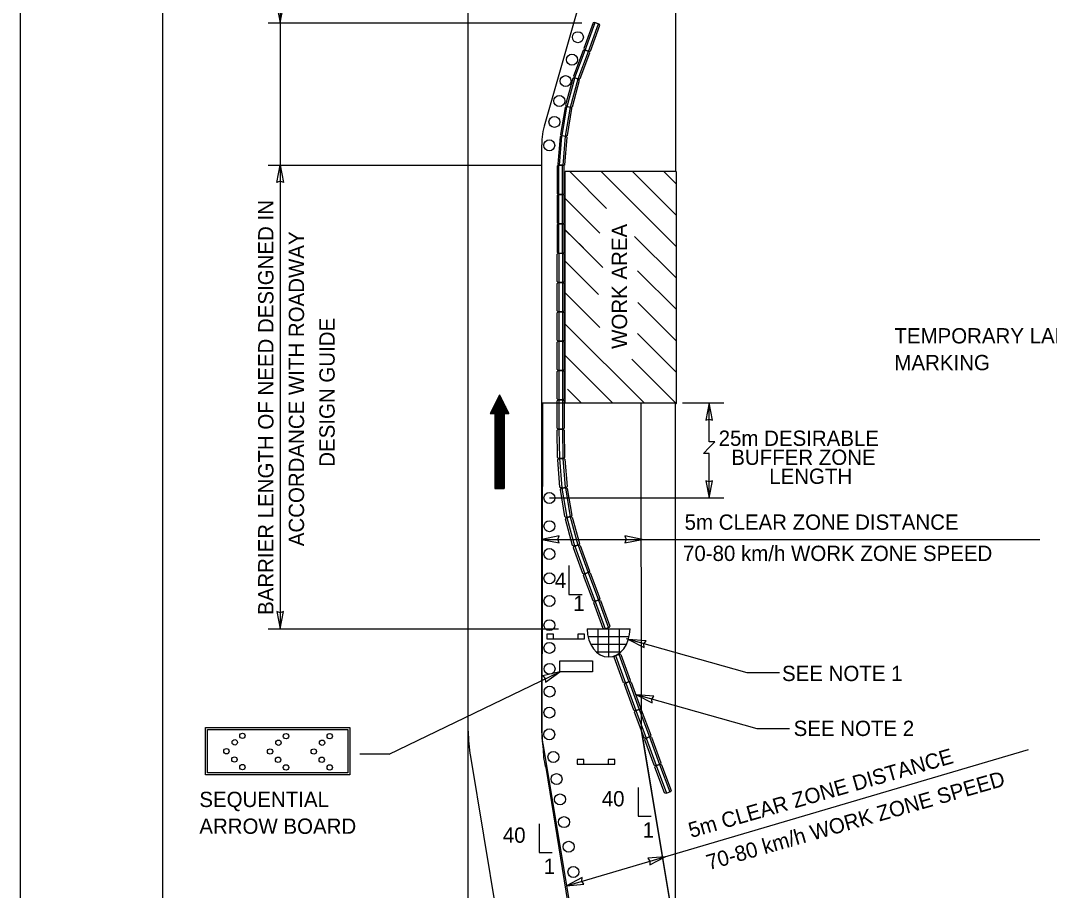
# Model space of a CAD drawing. Extents: x 3033 to 3249, y -403 to -124.
# Drawn here: x 3033.2 to 3167.7, y -305.8 to -192.1 of the extents above; entities that cross this region are included whole.
import ezdxf

# ---------------------------------------------------------------- set-up
doc = ezdxf.new("R2010")
doc.units = 0
for name, color, linetype in [('Level 10', 7, 'Continuous'), ('Level 17', 7, 'Continuous'), ('Level 20', 7, 'Continuous'), ('Level 22', 7, 'Continuous'), ('Level 4', 7, 'Continuous'), ('Level 44', 7, 'Continuous'), ('Level 5', 7, 'Continuous'), ('Level 60', 7, 'Continuous')]:
    doc.layers.add(name, color=color, linetype=linetype)

# ---------------------------------------------------------------- blocks, each defined once
blk = doc.blocks.new('arrow')
at = {"layer": 'Level 60'}
blk.add_lwpolyline([(0.6, 0.12), (0, 0), (0.6, -0.12), (0.56, 0)], close=True, dxfattribs=at)
blk = doc.blocks.new('BREAK')
at = {"layer": 'Level 20'}
blk.add_lwpolyline([(-12.499, 0), (-2.5, 0), (-2.5, 2.5), (0, 0), (2.501, -2.501), (2.501, 0), (12.501, 0)], dxfattribs=at)

msp = doc.modelspace()

# ---------------------------------------------------------------- linework, layer by layer
at = {"layer": 'Level 10'}
for p, q in [((3118.82, -141.45), (3118.82, -211.82)), ((3112.63, -167.28), (3101.72, -205.56)), ((3091.73, -284.98), (3091.73, -186.92)), ((3101.37, -285.2), (3101.34, -208.31)), ((3118.81, -211.82), (3104.41, -211.82)), ((3104.41, -242.11), (3104.41, -211.82)), ((3109.81, -216.64), (3104.99, -211.82)), ((3118.94, -221.66), (3109.1, -211.82)), ((3118.94, -217.55), (3113.2, -211.82)), ((3118.94, -213.45), (3117.31, -211.82)), ((3118.94, -242.11), (3118.94, -211.82)), ((3108.95, -219.88), (3104.41, -215.35)), ((3109.31, -224.35), (3104.41, -219.45)), ((3106.78, -221.81), (3104.42, -219.46)), ((3118.94, -225.77), (3113.48, -220.31)), ((3108.76, -227.9), (3104.41, -223.55)), ((3118.94, -229.87), (3113.84, -224.78)), ((3108.94, -232.19), (3104.41, -227.66)), ((3118.94, -233.98), (3113.89, -228.93)), ((3114.75, -242.11), (3104.41, -231.77)), ((3118.94, -238.08), (3113.86, -233.01)), ((3110.65, -242.11), (3104.41, -235.87)), ((3118.94, -242.19), (3113.11, -236.35)), ((3106.54, -242.11), (3104.72, -240.28)), ((3095.82, -241), (3094.6, -243.46)), ((3095.36, -241.92), (3095.36, -253.27)), ((3095.51, -241.62), (3095.51, -253.27)), ((3095.67, -241.31), (3095.67, -253.27)), ((3095.82, -241), (3095.82, -253.27)), ((3095.82, -241), (3097.05, -243.46)), ((3095.98, -241.31), (3095.98, -253.27)), ((3096.13, -241.62), (3096.13, -253.27)), ((3096.28, -241.92), (3096.28, -253.27)), ((3094.75, -243.15), (3094.75, -243.46)), ((3094.9, -242.84), (3094.9, -243.46)), ((3095.06, -242.54), (3095.06, -243.46)), ((3095.21, -242.23), (3095.21, -253.27)), ((3096.44, -242.23), (3096.44, -253.27)), ((3096.59, -242.54), (3096.59, -243.46)), ((3096.74, -242.84), (3096.74, -243.46)), ((3096.9, -243.15), (3096.9, -243.46)), ((3118.94, -242.11), (3104.41, -242.11)), ((3118.83, -370.96), (3118.83, -242.11)), ((3094.6, -243.46), (3095.21, -243.46)), ((3095.21, -243.46), (3095.21, -253.27)), ((3096.44, -243.46), (3096.44, -253.27)), ((3096.44, -243.46), (3097.05, -243.46)), ((3095.21, -253.27), (3096.44, -253.27)), ((3091.73, -370.96), (3091.73, -261.76)), ((3101.51, -286.84), (3112.75, -354.13)), ((3092.01, -288.27), (3097.4, -320.57)), ((3101.92, -289.97), (3112.2, -353.34))]:
    msp.add_line(p, q, dxfattribs=at)
msp.add_lwpolyline([(3113.02, -358.31), (3113.02, -370.96), (3126.02, -370.96), (3126.02, -354.69), (3114.37, -284.95), (3114.35, -242.11), (3101.45, -242.09), (3101.37, -285.85), (3101.52, -287.39)], dxfattribs=at)
msp.add_lwpolyline([(3103.7, -275.79), (3107.99, -275.79), (3107.99, -277.22), (3103.7, -277.22)], close=True, dxfattribs=at)
for centre in [(3106.06, -194.25), (3105.29, -197.19), (3104.45, -199.99), (3103.63, -202.59), (3103, -205.33), (3102.32, -208.39), (3102.34, -254.49), (3102.34, -258.18), (3102.34, -261.82), (3102.34, -264.99), (3102.34, -267.96), (3102.34, -271.12), (3102.34, -274.09), (3102.36, -276.83), (3102.36, -279.8), (3102.34, -282.55), (3102.32, -285.4), (3102.86, -288.35), (3103.27, -291.24), (3103.73, -293.9), (3104.25, -296.87), (3104.86, -300.09), (3105.48, -303.39)]:
    msp.add_circle(centre, 0.718, dxfattribs=at)
for centre, radius, start, end in [((3111.34, -208.3), 10, 164.0903, 180.023), ((3111.73, -284.98), 20, 180, 189.4843), ((3111.37, -285.2), 10, 180.023, 189.4843), ((3110.52, -287.31), 9, 180.5479, 197.1897)]:
    msp.add_arc(centre, radius, start, end, dxfattribs=at)
at = {"layer": 'Level 17'}
msp.add_line((3033.21, -402.59), (3033.21, -123.59), dxfattribs=at)
at = {"layer": 'Level 22'}
msp.add_line((3051.75, -135.28), (3051.75, -391.78), dxfattribs=at)
at = {"layer": 'Level 4'}
for p, q in [((3108.07, -192.38), (3106.83, -195.74)), ((3107, -195.94), (3108.33, -192.34)), ((3107.43, -196.1), (3108.76, -192.5)), ((3107.7, -196.06), (3108.94, -192.7)), ((3108.24, -192.31), (3108.07, -192.38)), ((3108.86, -192.54), (3108.24, -192.31)), ((3108.94, -192.7), (3108.86, -192.54)), ((3106.74, -195.98), (3105.5, -199.34)), ((3105.67, -199.54), (3107, -195.94)), ((3106.1, -199.7), (3107.43, -196.1)), ((3106.37, -199.66), (3107.61, -196.3)), ((3106.91, -195.91), (3106.74, -195.98)), ((3106.83, -195.74), (3106.91, -195.91)), ((3107.53, -196.13), (3106.91, -195.91)), ((3106.91, -195.91), (3107.53, -196.13)), ((3107.7, -196.06), (3107.53, -196.13)), ((3107.61, -196.3), (3107.53, -196.13)), ((3105.4, -199.65), (3104.46, -203.1)), ((3104.64, -203.29), (3105.65, -199.59)), ((3105.09, -203.41), (3106.1, -199.7)), ((3105.35, -203.34), (3106.29, -199.89)), ((3105.56, -199.56), (3105.4, -199.65)), ((3105.5, -199.34), (3105.58, -199.5)), ((3106.2, -199.73), (3105.56, -199.56)), ((3105.58, -199.5), (3106.2, -199.73)), ((3106.37, -199.66), (3106.2, -199.73)), ((3106.29, -199.89), (3106.2, -199.73)), ((3104.38, -203.43), (3103.79, -206.96)), ((3104, -207.12), (3104.63, -203.34)), ((3104.53, -203.32), (3104.38, -203.43)), ((3104.45, -207.2), (3105.08, -203.41)), ((3104.46, -203.1), (3104.55, -203.26)), ((3105.18, -203.43), (3104.53, -203.32)), ((3104.55, -203.26), (3105.19, -203.43)), ((3104.71, -207.1), (3105.29, -203.58)), ((3105.29, -203.58), (3105.18, -203.43)), ((3105.35, -203.34), (3105.19, -203.43)), ((3103.79, -206.96), (3103.9, -207.11)), ((3103.74, -207.28), (3103.45, -210.84)), ((3103.67, -210.99), (3103.98, -207.17)), ((3103.88, -207.16), (3103.74, -207.28)), ((3104.54, -207.22), (3103.88, -207.16)), ((3103.9, -207.11), (3104.56, -207.21)), ((3104.13, -211.03), (3104.44, -207.21)), ((3104.37, -210.92), (3104.66, -207.36)), ((3104.66, -207.36), (3104.54, -207.22)), ((3104.71, -207.1), (3104.56, -207.21)), ((3103.47, -210.98), (3103.34, -211.11)), ((3103.34, -211.11), (3103.34, -214.69)), ((3103.45, -210.84), (3103.57, -210.99)), ((3104.13, -210.99), (3103.47, -210.98)), ((3103.57, -214.82), (3103.57, -210.99)), ((3103.57, -210.99), (3104.23, -211.04)), ((3104.03, -214.82), (3104.03, -210.98)), ((3104.26, -211.11), (3104.13, -210.99)), ((3104.37, -210.92), (3104.23, -211.04)), ((3104.27, -214.69), (3104.26, -211.11)), ((3103.34, -214.69), (3103.47, -214.82)), ((3103.47, -214.82), (3103.34, -214.95)), ((3103.34, -214.95), (3103.35, -218.53)), ((3104.14, -214.82), (3103.47, -214.82)), ((3103.47, -214.82), (3104.14, -214.82)), ((3103.58, -218.66), (3103.57, -214.82)), ((3104.04, -218.66), (3104.03, -214.82)), ((3104.27, -214.69), (3104.14, -214.82)), ((3104.27, -214.95), (3104.14, -214.82)), ((3104.27, -218.53), (3104.27, -214.95)), ((3103.47, -218.65), (3103.34, -218.78)), ((3103.34, -218.78), (3103.35, -222.36)), ((3103.35, -218.53), (3103.48, -218.66)), ((3104.14, -218.65), (3103.47, -218.65)), ((3103.48, -218.66), (3104.14, -218.66)), ((3103.58, -222.49), (3103.57, -218.65)), ((3104.04, -222.49), (3104.03, -218.65)), ((3104.27, -218.53), (3104.14, -218.66)), ((3104.27, -218.78), (3104.14, -218.65)), ((3104.27, -222.36), (3104.27, -218.78)), ((3103.34, -226.2), (3103.35, -222.62)), ((3103.35, -222.36), (3103.48, -222.49)), ((3103.35, -222.62), (3103.48, -222.49)), ((3103.48, -222.49), (3104.14, -222.5)), ((3103.48, -222.49), (3104.14, -222.49)), ((3103.58, -222.49), (3103.57, -226.33)), ((3104.04, -222.49), (3104.03, -226.33)), ((3104.27, -222.36), (3104.14, -222.49)), ((3104.27, -222.62), (3104.14, -222.5)), ((3104.27, -222.62), (3104.27, -226.2)), ((3103.47, -226.33), (3103.34, -226.2)), ((3103.34, -230.03), (3103.35, -226.45)), ((3103.35, -226.45), (3103.48, -226.32)), ((3104.14, -226.33), (3103.47, -226.33)), ((3103.48, -226.32), (3104.14, -226.33)), ((3103.58, -226.32), (3103.57, -230.16)), ((3104.04, -226.32), (3104.03, -230.16)), ((3104.27, -226.2), (3104.14, -226.33)), ((3104.27, -226.45), (3104.14, -226.33)), ((3104.27, -226.45), (3104.27, -230.03)), ((3103.47, -230.16), (3103.34, -230.03)), ((3103.34, -233.86), (3103.35, -230.28)), ((3103.35, -230.28), (3103.48, -230.15)), ((3104.14, -230.16), (3103.47, -230.16)), ((3103.48, -230.15), (3104.14, -230.16)), ((3103.58, -230.15), (3103.57, -233.99)), ((3104.04, -230.15), (3104.03, -233.99)), ((3104.27, -230.03), (3104.14, -230.16)), ((3104.27, -230.28), (3104.14, -230.16)), ((3104.27, -230.28), (3104.27, -233.86)), ((3103.47, -233.99), (3103.34, -233.86)), ((3103.35, -234.11), (3103.48, -233.98)), ((3104.14, -233.99), (3103.47, -233.99)), ((3103.48, -233.98), (3104.14, -233.99)), ((3103.58, -233.98), (3103.57, -237.82)), ((3104.04, -233.98), (3104.03, -237.82)), ((3104.27, -233.86), (3104.14, -233.99)), ((3104.27, -234.11), (3104.14, -233.99)), ((3103.34, -237.69), (3103.35, -234.11)), ((3104.27, -234.11), (3104.27, -237.69)), ((3103.47, -237.82), (3103.34, -237.69)), ((3103.34, -241.52), (3103.35, -237.95)), ((3103.35, -237.95), (3103.48, -237.82)), ((3104.14, -237.82), (3103.47, -237.82)), ((3103.48, -237.82), (3104.14, -237.82)), ((3103.58, -237.82), (3103.57, -241.65)), ((3104.04, -237.81), (3104.03, -241.65)), ((3104.27, -237.69), (3104.14, -237.82)), ((3104.27, -237.94), (3104.14, -237.82)), ((3104.27, -237.94), (3104.27, -241.52)), ((3103.47, -241.65), (3103.34, -241.52)), ((3103.34, -245.35), (3103.35, -241.78)), ((3103.35, -241.78), (3103.48, -241.65)), ((3104.14, -241.65), (3103.47, -241.65)), ((3103.48, -241.65), (3104.14, -241.65)), ((3103.58, -241.65), (3103.57, -245.48)), ((3104.04, -241.64), (3104.03, -245.48)), ((3104.27, -241.52), (3104.14, -241.65)), ((3104.27, -241.78), (3104.14, -241.65)), ((3104.27, -241.78), (3104.27, -245.35)), ((3103.47, -245.48), (3103.34, -245.35)), ((3103.35, -245.62), (3103.48, -245.49)), ((3103.41, -249.2), (3103.35, -245.62)), ((3104.14, -245.48), (3103.47, -245.48)), ((3103.48, -245.49), (3104.14, -245.48)), ((3103.58, -245.49), (3103.64, -249.32)), ((3104.04, -245.48), (3104.1, -249.32)), ((3104.27, -245.35), (3104.14, -245.48)), ((3104.27, -245.61), (3104.14, -245.48)), ((3104.27, -245.61), (3104.33, -249.18)), ((3103.54, -249.33), (3103.41, -249.2)), ((3103.42, -249.5), (3103.54, -249.36)), ((3103.72, -253.07), (3103.42, -249.5)), ((3103.54, -249.36), (3104.2, -249.31)), ((3104.2, -249.31), (3103.54, -249.33)), ((3103.64, -249.35), (3103.96, -253.18)), ((3104.1, -249.32), (3104.41, -253.14)), ((3104.33, -249.18), (3104.2, -249.31)), ((3104.35, -249.43), (3104.2, -249.31)), ((3104.35, -249.43), (3104.64, -252.99)), ((3103.86, -253.19), (3103.72, -253.07)), ((3103.77, -253.39), (3103.88, -253.24)), ((3104.35, -256.92), (3103.77, -253.39)), ((3104.52, -253.13), (3103.86, -253.19)), ((3103.88, -253.24), (3104.53, -253.14)), ((3103.98, -253.23), (3104.6, -257.01)), ((3104.43, -253.15), (3105.05, -256.94)), ((3104.64, -252.99), (3104.52, -253.13)), ((3104.68, -253.24), (3104.53, -253.14)), ((3104.68, -253.24), (3105.26, -256.77)), ((3105.26, -256.77), (3105.16, -256.92)), ((3104.5, -257.03), (3104.35, -256.92)), ((3104.43, -257.25), (3104.52, -257.09)), ((3105.37, -260.7), (3104.43, -257.25)), ((3105.16, -256.92), (3104.5, -257.03)), ((3104.52, -257.09), (3105.16, -256.91)), ((3104.62, -257.06), (3105.63, -260.76)), ((3105.06, -256.94), (3106.07, -260.64)), ((3105.32, -257.01), (3105.16, -256.91)), ((3105.32, -257.01), (3106.26, -260.45)), ((3105.53, -260.79), (3105.37, -260.7)), ((3105.47, -261.01), (3105.55, -260.84)), ((3106.17, -260.62), (3105.53, -260.79)), ((3105.55, -260.84), (3106.17, -260.62)), ((3105.65, -260.81), (3106.98, -264.41)), ((3106.08, -260.65), (3107.41, -264.25)), ((3106.26, -260.45), (3106.17, -260.62)), ((3106.34, -260.69), (3106.17, -260.62)), ((3106.34, -260.69), (3107.58, -264.05)), ((3106.71, -264.37), (3105.47, -261.01)), ((3106.88, -264.44), (3106.71, -264.37)), ((3106.81, -264.61), (3106.89, -264.44)), ((3108.05, -267.96), (3106.81, -264.61)), ((3107.5, -264.21), (3106.88, -264.44)), ((3106.89, -264.44), (3107.51, -264.21)), ((3106.98, -264.41), (3108.31, -268.01)), ((3107.41, -264.25), (3108.74, -267.85)), ((3107.58, -264.05), (3107.5, -264.21)), ((3107.68, -264.29), (3107.51, -264.21)), ((3107.68, -264.29), (3108.92, -267.64)), ((3108.22, -268.04), (3108.05, -267.96)), ((3108.14, -268.21), (3108.22, -268.04)), ((3109.38, -271.56), (3108.14, -268.21)), ((3108.84, -267.81), (3108.22, -268.04)), ((3108.22, -268.04), (3108.84, -267.81)), ((3108.31, -268.01), (3109.64, -271.6)), ((3108.74, -267.85), (3110.07, -271.45)), ((3108.92, -267.64), (3108.84, -267.81)), ((3109.01, -267.89), (3108.84, -267.81)), ((3109.01, -267.89), (3110.25, -271.24)), ((3107.26, -271.59), (3112.88, -271.59)), ((3108.67, -271.59), (3108.67, -274.78)), ((3109.55, -271.64), (3109.38, -271.56)), ((3110.17, -271.41), (3109.55, -271.64)), ((3110.07, -271.59), (3110.07, -275.27)), ((3110.25, -271.24), (3110.17, -271.41)), ((3111.47, -271.59), (3111.47, -274.78)), ((3107.37, -272.59), (3112.77, -272.59)), ((3107.72, -273.59), (3112.42, -273.59)), ((3108.44, -274.59), (3111.7, -274.59)), ((3110.8, -275.29), (3110.88, -275.12)), ((3112.04, -278.64), (3110.8, -275.29)), ((3110.88, -275.12), (3111.5, -274.89)), ((3110.97, -275.09), (3112.3, -278.69)), ((3111.4, -274.93), (3112.73, -278.53)), ((3111.67, -274.97), (3111.5, -274.89)), ((3111.67, -274.97), (3112.9, -278.32)), ((3112.9, -278.32), (3112.83, -278.49)), ((3112.21, -278.72), (3112.04, -278.64)), ((3112.15, -278.89), (3112.23, -278.72)), ((3113.39, -282.24), (3112.15, -278.89)), ((3112.83, -278.49), (3112.21, -278.72)), ((3112.23, -278.72), (3112.85, -278.49)), ((3112.32, -278.69), (3113.65, -282.28)), ((3112.75, -278.53), (3114.08, -282.13)), ((3113.02, -278.57), (3112.85, -278.49)), ((3113.02, -278.57), (3114.26, -281.92)), ((3113.56, -282.32), (3113.39, -282.24)), ((3113.48, -282.49), (3113.56, -282.32)), ((3114.18, -282.09), (3113.56, -282.32)), ((3113.56, -282.32), (3114.18, -282.09)), ((3113.65, -282.29), (3114.98, -285.88)), ((3114.08, -282.13), (3115.41, -285.73)), ((3114.26, -281.92), (3114.18, -282.09)), ((3114.35, -282.17), (3114.18, -282.09)), ((3114.35, -282.17), (3115.59, -285.52)), ((3114.72, -285.84), (3113.48, -282.49)), ((3114.89, -285.92), (3114.72, -285.84)), ((3114.81, -286.09), (3114.89, -285.92)), ((3116.05, -289.44), (3114.81, -286.09)), ((3115.51, -285.69), (3114.89, -285.92)), ((3114.89, -285.92), (3115.51, -285.69)), ((3114.98, -285.88), (3116.31, -289.48)), ((3115.41, -285.72), (3116.74, -289.32)), ((3115.59, -285.52), (3115.51, -285.69)), ((3115.68, -285.77), (3115.51, -285.69)), ((3115.68, -285.77), (3116.92, -289.12)), ((3116.92, -289.12), (3116.84, -289.29)), ((3116.22, -289.52), (3116.05, -289.44)), ((3116.14, -289.68), (3116.22, -289.52)), ((3117.38, -293.04), (3116.14, -289.68)), ((3116.84, -289.29), (3116.22, -289.52)), ((3116.22, -289.52), (3116.84, -289.29)), ((3116.31, -289.48), (3117.64, -293.08)), ((3116.74, -289.32), (3118.07, -292.92)), ((3117.01, -289.36), (3116.84, -289.29)), ((3117.01, -289.36), (3118.25, -292.72)), ((3117.55, -293.11), (3117.38, -293.04)), ((3118.17, -292.89), (3117.55, -293.11)), ((3118.25, -292.72), (3118.17, -292.89))]:
    msp.add_line(p, q, dxfattribs=at)
msp.add_ellipse((3110.07, -271.58), major_axis=(0, -3.7), ratio=0.758621, start_param=4.716532, end_param=7.849839, dxfattribs=at)
at = {"layer": 'Level 44'}
for p, q in [((3057.38, -290.7), (3057.38, -284.5)), ((3057.38, -284.5), (3076.25, -284.5)), ((3057.66, -290.41), (3057.66, -284.78)), ((3057.66, -284.78), (3075.97, -284.78)), ((3075.97, -284.78), (3075.97, -290.41)), ((3076.25, -284.5), (3076.25, -290.7)), ((3075.97, -290.41), (3057.66, -290.41)), ((3076.25, -290.7), (3057.38, -290.7))]:
    msp.add_line(p, q, dxfattribs=at)
for centre in [(3061.21, -286.44), (3062.21, -285.59), (3066.92, -286.49), (3067.91, -285.63), (3072.62, -286.49), (3073.62, -285.63), (3060.12, -287.6), (3065.83, -287.64), (3071.54, -287.64), (3061.17, -288.68), (3066.87, -288.72), (3072.58, -288.72), (3062.21, -289.68), (3067.91, -289.72), (3073.62, -289.72)]:
    msp.add_circle(centre, 0.351, dxfattribs=at)
at = {"layer": 'Level 5'}
for p, q in [((3067.15, -163.02), (3067.15, -271.59)), ((3065.57, -192.38), (3106.58, -192.38)), ((3065.57, -210.99), (3101.34, -210.99)), ((3114.37, -284.95), (3114.35, -242.11)), ((3119.72, -242.07), (3125.12, -242.07)), ((3123.22, -245.9), (3123.22, -242.07)), ((3123.22, -254.49), (3123.22, -249.69)), ((3102.34, -254.49), (3125.12, -254.49)), ((3101.36, -259.91), (3166.44, -259.91)), ((3104.89, -263.33), (3104.89, -267.09)), ((3104.89, -267.09), (3106.6, -267.09)), ((3065.57, -271.59), (3103.51, -271.59)), ((3102.89, -272.29), (3102.02, -272.29)), ((3102.02, -272.29), (3102.02, -272.9)), ((3102.02, -272.9), (3106.94, -272.9)), ((3102.89, -272.9), (3102.89, -272.29)), ((3106.94, -272.29), (3106.07, -272.29)), ((3106.07, -272.29), (3106.07, -272.9)), ((3106.94, -272.9), (3106.94, -272.29)), ((3081.41, -287.99), (3103.7, -277.22)), ((3114.37, -284.95), (3126.02, -354.69)), ((3104.57, -305.2), (3164.94, -287.37)), ((3081.41, -287.99), (3077.57, -287.99)), ((3106.83, -288.7), (3105.95, -288.7)), ((3105.95, -288.7), (3105.95, -289.31)), ((3106.83, -289.31), (3106.83, -288.7)), ((3110.88, -288.7), (3110.01, -288.7)), ((3110.01, -288.7), (3110.01, -289.31)), ((3110.88, -289.31), (3110.88, -288.7)), ((3105.95, -289.31), (3110.88, -289.31)), ((3113.93, -292.35), (3113.93, -296.1)), ((3101, -297.1), (3101, -300.86)), ((3113.93, -296.1), (3115.64, -296.1)), ((3101, -300.86), (3102.71, -300.86))]:
    msp.add_line(p, q, dxfattribs=at)
for points in [[(3132.43, -277.35), (3128.2, -277.35), (3112.42, -272.91)], [(3133.72, -284.68), (3129.49, -284.68), (3113.71, -280.24)]]:
    msp.add_lwpolyline(points, dxfattribs=at)

# ---------------------------------------------------------------- block references
at = {"layer": 'Level 10', "xscale": 3.75}
for p, yscale, rotation in [((3067.14, -192.37), 3.75, 90), ((3067.15, -210.99), -3.75, -90), ((3123.22, -242.07), 3.75, -90), ((3123.22, -254.49), 3.75, 90), ((3067.15, -271.59), 3.75, 90)]:
    msp.add_blockref('arrow', p, dxfattribs=dict(at, yscale=yscale, rotation=rotation))
at = {"layer": 'Level 5'}
for name, p, xscale, yscale, rotation in [('BREAK', (3123.21, -247.91), 0.30000000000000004, 0.30000000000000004, 90), ('arrow', (3114.45, -259.9), 3.75, 3.75, 180), ('arrow', (3112.68, -272.98), 3.750000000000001, 3.7500000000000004, -15.697792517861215), ('arrow', (3103.7, -277.22), 3.7500000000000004, 3.7499999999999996, -155.24050793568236), ('arrow', (3113.71, -280.24), 3.750000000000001, 3.7500000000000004, -15.697792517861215), ('arrow', (3117.48, -301.39), 3.7499999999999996, 3.7500000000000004, -163.54106952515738), ('arrow', (3104.57, -305.2), 3.7499999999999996, 3.7500000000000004, 16.458930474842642)]:
    msp.add_blockref(name, p, dxfattribs=dict(at, xscale=xscale, yscale=yscale, rotation=rotation))
at = {"layer": 'Level 5', "xscale": 3.75, "yscale": 3.75}
msp.add_blockref('arrow', (3101.36, -259.91), dxfattribs=at)

# ---------------------------------------------------------------- texts
at = {"layer": 'Level 10'}
msp.add_text('WORK AREA', height=2, rotation=90, dxfattribs=at).set_placement((3112.49, -235))
at = {"layer": 'Level 44'}
for s, rotation, p in [('BARRIER LENGTH OF NEED DESIGNED IN', 90, (3066.27, -269.78)), ('ACCORDANCE WITH ROADWAY', 90, (3070.27, -260.8)), ('DESIGN GUIDE', 90, (3074.27, -250.41)), ('25m DESIRABLE', 360, (3124.46, -247.68)), ('BUFFER ZONE', 360, (3126.11, -250.17)), ('LENGTH', 360, (3131.07, -252.65))]:
    msp.add_text(s, height=2, rotation=rotation, dxfattribs=at).set_placement(p)
at = {"layer": 'Level 5'}
for s, p in [('TEMPORARY LANE', (3147.43, -234.29)), ('MARKING', (3147.43, -237.79)), ('70-80 km/h WORK ZONE SPEED', (3119.8, -262.73)), ('4', (3103.04, -266.26)), ('1', (3105.45, -269.27)), ('SEE NOTE 1', (3132.74, -278.43)), ('SEE NOTE 2', (3134.26, -285.61)), ('40', (3109.18, -294.81)), ('1', (3114.53, -298.89)), ('40', (3096.25, -299.57)), ('1', (3101.6, -303.64))]:
    msp.add_text(s, height=2, dxfattribs=at).set_placement(p)
for s, rotation, p in [('5m CLEAR ZONE DISTANCE', 360, (3120.01, -258.65)), ('5m CLEAR ZONE DISTANCE', 15.9427, (3120.85, -298.95)), ('70-80 km/h WORK ZONE SPEED', 15.9427, (3123.18, -303.16)), ('SEQUENTIAL', 0, (3056.58, -294.9)), ('ARROW BOARD', 0, (3056.58, -298.4))]:
    msp.add_text(s, height=2, rotation=rotation, dxfattribs=at).set_placement(p)

doc.saveas('drawing.dxf')
